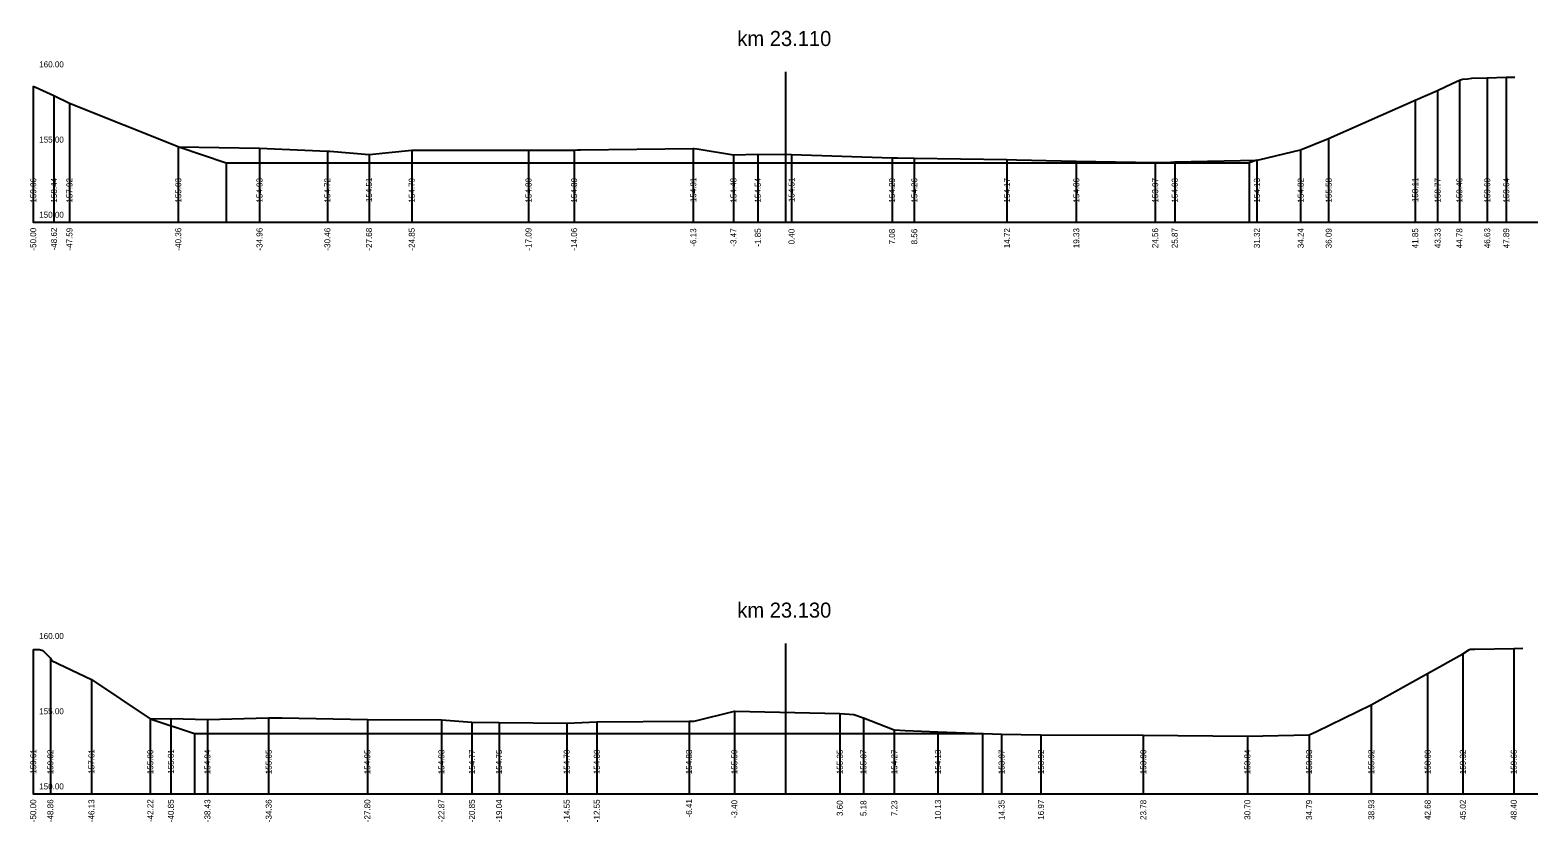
# Model space of a CAD drawing. Extents: x -582678 to -581845, y -1210354 to -1210235.
# Drawn here: x -581945.7 to -581845.4, y -1210306.7 to -1210254.1 of the extents above; entities that cross this region are included whole.
import ezdxf

# ---------------------------------------------------------------- set-up
doc = ezdxf.new("R2010")
doc.units = 0
for name, color, linetype in [('_N_osa', 7, 'Continuous'), ('_N_pomocná', 7, 'Continuous'), ('_N_tučná', 7, 'Continuous'), ('_S_popis', 7, 'Continuous'), ('_S_popis_oprav!', 7, 'Continuous'), ('_S_tenká', 7, 'Continuous'), ('_S_velmi_tenká', 7, 'Continuous')]:
    doc.layers.add(name, color=color, linetype=linetype)

msp = doc.modelspace()

# ---------------------------------------------------------------- linework, layer by layer
at = {"layer": '_N_osa'}
for p, q in [((-581895.45, -1210256.87), (-581895.45, -1210266.87)), ((-581895.45, -1210294.87), (-581895.45, -1210304.87))]:
    msp.add_line(p, q, dxfattribs=at)
at = {"layer": '_N_pomocná'}
for p, q in [((-581932.63, -1210262.91), (-581932.63, -1210266.87)), ((-581864.63, -1210262.91), (-581864.63, -1210266.87)), ((-581934.72, -1210300.85), (-581934.72, -1210304.87)), ((-581882.35, -1210300.85), (-581882.35, -1210304.87))]:
    msp.add_line(p, q, dxfattribs=at)
at = {"layer": '_N_tučná'}
for p, q in [((-581935.78, -1210261.85), (-581932.63, -1210262.91)), ((-581864.12, -1210262.74), (-581864.63, -1210262.91)), ((-581937.67, -1210299.87), (-581934.72, -1210300.85))]:
    msp.add_line(p, q, dxfattribs=at)
for points in [[(-581932.63, -1210262.91), (-581864.63, -1210262.91)], [(-581934.72, -1210300.85), (-581882.35, -1210300.85)]]:
    msp.add_lwpolyline(points, dxfattribs=at)
at = {"layer": '_S_tenká'}
for p, q in [((-581945.45, -1210266.87), (-581845.45, -1210266.87)), ((-581945.45, -1210304.87), (-581845.45, -1210304.87))]:
    msp.add_line(p, q, dxfattribs=at)
for points in [[(-581945.45, -1210257.81), (-581945.3, -1210257.88), (-581944.07, -1210258.43), (-581943.04, -1210258.95), (-581935.81, -1210261.84), (-581935.78, -1210261.85), (-581935.77, -1210261.85), (-581930.41, -1210261.94), (-581925.9, -1210262.15), (-581925.73, -1210262.14), (-581923.13, -1210262.36), (-581920.29, -1210262.08), (-581919.97, -1210262.07), (-581912.53, -1210262.07), (-581909.5, -1210262.07), (-581909.42, -1210262.07), (-581909.27, -1210262.06), (-581909.07, -1210262.06), (-581901.58, -1210261.96), (-581901.52, -1210261.96), (-581901.32, -1210261.99), (-581898.91, -1210262.39), (-581897.29, -1210262.33), (-581895.05, -1210262.36), (-581888.37, -1210262.58), (-581888.01, -1210262.59), (-581886.89, -1210262.61), (-581880.73, -1210262.7), (-581880.1, -1210262.71), (-581876.12, -1210262.81), (-581870.88, -1210262.9), (-581870.12, -1210262.89), (-581869.58, -1210262.84), (-581864.12, -1210262.74), (-581863.9, -1210262.7), (-581861.21, -1210262.05), (-581859.35, -1210261.29), (-581853.6, -1210258.76), (-581852.11, -1210258.1), (-581851.13, -1210257.64), (-581850.66, -1210257.41), (-581850.45, -1210257.35), (-581850.12, -1210257.34), (-581849.83, -1210257.29), (-581848.81, -1210257.27), (-581847.55, -1210257.23), (-581847.12, -1210257.22), (-581846.98, -1210257.22)], [(-581945.45, -1210295.26), (-581945.35, -1210295.26), (-581945.03, -1210295.27), (-581944.8, -1210295.34), (-581944.31, -1210295.85), (-581944.23, -1210296), (-581941.58, -1210297.26), (-581937.67, -1210299.87), (-581936.3, -1210299.86), (-581933.87, -1210299.93), (-581929.8, -1210299.82), (-581929.36, -1210299.82), (-581928.93, -1210299.82), (-581923.24, -1210299.92), (-581918.32, -1210299.94), (-581916.29, -1210300.1), (-581914.49, -1210300.12), (-581909.99, -1210300.17), (-581907.99, -1210300.07), (-581901.86, -1210300.04), (-581901.6, -1210300.04), (-581901.53, -1210300.03), (-581898.85, -1210299.37), (-581898.81, -1210299.37), (-581891.84, -1210299.52), (-581890.9, -1210299.58), (-581890.27, -1210299.8), (-581888.22, -1210300.6), (-581887.5, -1210300.65), (-581885.32, -1210300.74), (-581881.09, -1210300.9), (-581878.47, -1210300.95), (-581871.67, -1210300.97), (-581864.75, -1210301.03), (-581860.65, -1210300.94), (-581860.16, -1210300.71), (-581856.52, -1210298.95), (-581852.77, -1210296.87), (-581850.43, -1210295.55), (-581849.99, -1210295.27), (-581849.93, -1210295.25), (-581849.64, -1210295.24), (-581847.05, -1210295.21), (-581846.45, -1210295.18)]]:
    msp.add_lwpolyline(points, dxfattribs=at)
at = {"layer": '_S_velmi_tenká'}
for points in [[(-581850.66, -1210257.41), (-581850.66, -1210266.87), (-581850.66, -1210266.87), (-581850.66, -1210266.87)], [(-581848.81, -1210257.27), (-581848.81, -1210266.87), (-581848.81, -1210266.87), (-581848.81, -1210266.87)], [(-581847.55, -1210257.23), (-581847.55, -1210266.87), (-581847.55, -1210266.87), (-581847.55, -1210266.87)], [(-581945.45, -1210257.81), (-581945.45, -1210266.87), (-581945.45, -1210266.87), (-581945.45, -1210266.87)], [(-581944.07, -1210258.43), (-581944.07, -1210266.87), (-581944.07, -1210266.87), (-581944.07, -1210266.87)], [(-581852.11, -1210258.1), (-581852.11, -1210266.87), (-581852.11, -1210266.87), (-581852.11, -1210266.87)], [(-581943.04, -1210258.95), (-581943.04, -1210266.87), (-581943.04, -1210266.87), (-581943.04, -1210266.87)], [(-581853.6, -1210258.76), (-581853.6, -1210266.87), (-581853.6, -1210266.87), (-581853.6, -1210266.87)], [(-581859.35, -1210261.29), (-581859.35, -1210266.87), (-581859.35, -1210266.87), (-581859.35, -1210266.87)], [(-581935.81, -1210261.84), (-581935.81, -1210266.87), (-581935.81, -1210266.87), (-581935.81, -1210266.87)], [(-581930.41, -1210261.94), (-581930.41, -1210266.87), (-581930.41, -1210266.87), (-581930.41, -1210266.87)], [(-581925.9, -1210262.15), (-581925.9, -1210266.87), (-581925.9, -1210266.87), (-581925.9, -1210266.87)], [(-581923.13, -1210262.36), (-581923.13, -1210266.87), (-581923.13, -1210266.87), (-581923.13, -1210266.87)], [(-581920.29, -1210262.08), (-581920.29, -1210266.87), (-581920.29, -1210266.87), (-581920.29, -1210266.87)], [(-581912.53, -1210262.07), (-581912.53, -1210266.87), (-581912.53, -1210266.87), (-581912.53, -1210266.87)], [(-581909.5, -1210262.07), (-581909.5, -1210266.87), (-581909.5, -1210266.87), (-581909.5, -1210266.87)], [(-581901.58, -1210261.96), (-581901.58, -1210266.87), (-581901.58, -1210266.87), (-581901.58, -1210266.87)], [(-581898.91, -1210262.39), (-581898.91, -1210266.87), (-581898.91, -1210266.87), (-581898.91, -1210266.87)], [(-581897.29, -1210262.33), (-581897.29, -1210266.87), (-581897.29, -1210266.87), (-581897.29, -1210266.87)], [(-581895.05, -1210262.36), (-581895.05, -1210266.87), (-581895.05, -1210266.87), (-581895.05, -1210266.87)], [(-581861.21, -1210262.05), (-581861.21, -1210266.87), (-581861.21, -1210266.87), (-581861.21, -1210266.87)], [(-581888.37, -1210262.58), (-581888.37, -1210266.87), (-581888.37, -1210266.87), (-581888.37, -1210266.87)], [(-581886.89, -1210262.61), (-581886.89, -1210266.87), (-581886.89, -1210266.87), (-581886.89, -1210266.87)], [(-581880.73, -1210262.7), (-581880.73, -1210266.87), (-581880.73, -1210266.87), (-581880.73, -1210266.87)], [(-581876.12, -1210262.81), (-581876.12, -1210266.87), (-581876.12, -1210266.87), (-581876.12, -1210266.87)], [(-581870.88, -1210262.9), (-581870.88, -1210266.87), (-581870.88, -1210266.87), (-581870.88, -1210266.87)], [(-581869.58, -1210262.84), (-581869.58, -1210266.87), (-581869.58, -1210266.87), (-581869.58, -1210266.87)], [(-581864.12, -1210262.74), (-581864.12, -1210266.87), (-581864.12, -1210266.87), (-581864.12, -1210266.87)], [(-581945.45, -1210295.26), (-581945.45, -1210304.87), (-581945.45, -1210304.87), (-581945.45, -1210304.87)], [(-581850.43, -1210295.55), (-581850.43, -1210304.87), (-581850.43, -1210304.87), (-581850.43, -1210304.87)], [(-581847.05, -1210295.21), (-581847.05, -1210304.87), (-581847.05, -1210304.87), (-581847.05, -1210304.87)], [(-581944.31, -1210295.85), (-581944.31, -1210304.87), (-581944.31, -1210304.87), (-581944.31, -1210304.87)], [(-581941.58, -1210297.26), (-581941.58, -1210304.87), (-581941.58, -1210304.87), (-581941.58, -1210304.87)], [(-581852.77, -1210296.87), (-581852.77, -1210304.87), (-581852.77, -1210304.87), (-581852.77, -1210304.87)], [(-581898.85, -1210299.37), (-581898.85, -1210304.87), (-581898.85, -1210304.87), (-581898.85, -1210304.87)], [(-581891.84, -1210299.52), (-581891.84, -1210304.87), (-581891.84, -1210304.87), (-581891.84, -1210304.87)], [(-581856.52, -1210298.95), (-581856.52, -1210304.87), (-581856.52, -1210304.87), (-581856.52, -1210304.87)], [(-581937.67, -1210299.87), (-581937.67, -1210304.87), (-581937.67, -1210304.87), (-581937.67, -1210304.87)], [(-581936.3, -1210299.86), (-581936.3, -1210304.87), (-581936.3, -1210304.87), (-581936.3, -1210304.87)], [(-581933.87, -1210299.93), (-581933.87, -1210304.87), (-581933.87, -1210304.87), (-581933.87, -1210304.87)], [(-581929.8, -1210299.82), (-581929.8, -1210304.87), (-581929.8, -1210304.87), (-581929.8, -1210304.87)], [(-581923.24, -1210299.92), (-581923.24, -1210304.87), (-581923.24, -1210304.87), (-581923.24, -1210304.87)], [(-581918.32, -1210299.94), (-581918.32, -1210304.87), (-581918.32, -1210304.87), (-581918.32, -1210304.87)], [(-581916.29, -1210300.1), (-581916.29, -1210304.87), (-581916.29, -1210304.87), (-581916.29, -1210304.87)], [(-581914.49, -1210300.12), (-581914.49, -1210304.87), (-581914.49, -1210304.87), (-581914.49, -1210304.87)], [(-581909.99, -1210300.17), (-581909.99, -1210304.87), (-581909.99, -1210304.87), (-581909.99, -1210304.87)], [(-581907.99, -1210300.07), (-581907.99, -1210304.87), (-581907.99, -1210304.87), (-581907.99, -1210304.87)], [(-581901.86, -1210300.04), (-581901.86, -1210304.87), (-581901.86, -1210304.87), (-581901.86, -1210304.87)], [(-581890.27, -1210299.8), (-581890.27, -1210304.87), (-581890.27, -1210304.87), (-581890.27, -1210304.87)], [(-581888.22, -1210300.6), (-581888.22, -1210304.87), (-581888.22, -1210304.87), (-581888.22, -1210304.87)], [(-581885.32, -1210300.74), (-581885.32, -1210304.87), (-581885.32, -1210304.87), (-581885.32, -1210304.87)], [(-581881.09, -1210300.9), (-581881.09, -1210304.87), (-581881.09, -1210304.87), (-581881.09, -1210304.87)], [(-581878.47, -1210300.95), (-581878.47, -1210304.87), (-581878.47, -1210304.87), (-581878.47, -1210304.87)], [(-581871.67, -1210300.97), (-581871.67, -1210304.87), (-581871.67, -1210304.87), (-581871.67, -1210304.87)], [(-581864.75, -1210301.03), (-581864.75, -1210304.87), (-581864.75, -1210304.87), (-581864.75, -1210304.87)], [(-581860.65, -1210300.94), (-581860.65, -1210304.87), (-581860.65, -1210304.87), (-581860.65, -1210304.87)]]:
    msp.add_lwpolyline(points, dxfattribs=at)

# ---------------------------------------------------------------- texts
at = {"layer": '_S_popis'}
for s, p in [('160.00', (-581945.05, -1210256.57)), ('155.00', (-581945.05, -1210261.57)), ('150.00', (-581945.05, -1210266.57)), ('160.00', (-581945.05, -1210294.57)), ('155.00', (-581945.05, -1210299.57)), ('150.00', (-581945.05, -1210304.57))]:
    msp.add_text(s, height=0.4, dxfattribs=at).set_placement(p)
for s, p in [('159.06', (-581945.25, -1210265.56)), ('158.44', (-581943.87, -1210265.56)), ('157.92', (-581942.84, -1210265.56)), ('155.03', (-581935.61, -1210265.56)), ('154.93', (-581930.21, -1210265.56)), ('154.72', (-581925.7, -1210265.56)), ('154.51', (-581922.93, -1210265.53)), ('154.79', (-581920.09, -1210265.56)), ('154.80', (-581912.33, -1210265.56)), ('154.80', (-581909.3, -1210265.56)), ('154.91', (-581901.38, -1210265.53)), ('154.48', (-581898.71, -1210265.56)), ('154.54', (-581897.09, -1210265.56)), ('154.51', (-581894.85, -1210265.53)), ('154.29', (-581888.17, -1210265.56)), ('154.26', (-581886.69, -1210265.56)), ('154.17', (-581880.53, -1210265.56)), ('154.06', (-581875.92, -1210265.56)), ('153.97', (-581870.68, -1210265.56)), ('154.03', (-581869.38, -1210265.56)), ('154.13', (-581863.92, -1210265.56)), ('154.82', (-581861.01, -1210265.56)), ('155.58', (-581859.15, -1210265.56)), ('158.11', (-581853.4, -1210265.53)), ('158.77', (-581851.91, -1210265.56)), ('159.46', (-581850.46, -1210265.56)), ('159.60', (-581848.61, -1210265.56)), ('159.64', (-581847.35, -1210265.56)), ('-50.00', (-581945.25, -1210268.75)), ('-48.62', (-581943.87, -1210268.74)), ('-47.59', (-581942.84, -1210268.75)), ('-40.36', (-581935.61, -1210268.75)), ('-34.96', (-581930.21, -1210268.75)), ('-30.46', (-581925.7, -1210268.75)), ('-27.68', (-581922.93, -1210268.75)), ('-24.85', (-581920.09, -1210268.75)), ('-17.09', (-581912.33, -1210268.75)), ('-14.06', (-581909.3, -1210268.75)), ('-6.13', (-581901.38, -1210268.49)), ('-3.47', (-581898.71, -1210268.49)), ('-1.85', (-581897.09, -1210268.49)), ('0.40', (-581894.85, -1210268.34)), ('7.08', (-581888.17, -1210268.34)), ('8.56', (-581886.69, -1210268.34)), ('14.72', (-581880.53, -1210268.59)), ('19.33', (-581875.92, -1210268.59)), ('24.56', (-581870.68, -1210268.59)), ('25.87', (-581869.38, -1210268.59)), ('31.32', (-581863.92, -1210268.59)), ('34.24', (-581861.01, -1210268.59)), ('36.09', (-581859.15, -1210268.6)), ('41.85', (-581853.4, -1210268.6)), ('43.33', (-581851.91, -1210268.59)), ('44.78', (-581850.46, -1210268.6)), ('46.63', (-581848.61, -1210268.59)), ('47.89', (-581847.35, -1210268.6)), ('159.61', (-581945.25, -1210303.53)), ('159.02', (-581944.11, -1210303.56)), ('157.61', (-581941.38, -1210303.53)), ('155.00', (-581937.47, -1210303.56)), ('155.01', (-581936.1, -1210303.53)), ('154.94', (-581933.67, -1210303.56)), ('155.05', (-581929.6, -1210303.56)), ('154.95', (-581923.04, -1210303.56)), ('154.93', (-581918.12, -1210303.56)), ('154.77', (-581916.09, -1210303.56)), ('154.75', (-581914.29, -1210303.56)), ('154.70', (-581909.79, -1210303.56)), ('154.80', (-581907.79, -1210303.56)), ('154.83', (-581901.66, -1210303.56)), ('155.50', (-581898.65, -1210303.56)), ('155.35', (-581891.64, -1210303.56)), ('155.07', (-581890.07, -1210303.56)), ('154.27', (-581888.02, -1210303.56)), ('154.13', (-581885.12, -1210303.56)), ('153.97', (-581880.89, -1210303.56)), ('153.92', (-581878.27, -1210303.56)), ('153.90', (-581871.47, -1210303.56)), ('153.84', (-581864.55, -1210303.56)), ('153.93', (-581860.45, -1210303.56)), ('155.92', (-581856.32, -1210303.56)), ('158.00', (-581852.57, -1210303.56)), ('159.32', (-581850.23, -1210303.56)), ('159.66', (-581846.85, -1210303.56)), ('-50.00', (-581945.25, -1210306.75)), ('-48.86', (-581944.11, -1210306.75)), ('-46.13', (-581941.38, -1210306.75)), ('-42.22', (-581937.47, -1210306.74)), ('-40.85', (-581936.1, -1210306.75)), ('-38.43', (-581933.67, -1210306.75)), ('-34.36', (-581929.6, -1210306.75)), ('-27.80', (-581923.04, -1210306.75)), ('-22.87', (-581918.12, -1210306.75)), ('-20.85', (-581916.09, -1210306.75)), ('-19.04', (-581914.29, -1210306.75)), ('-14.55', (-581909.79, -1210306.75)), ('-12.55', (-581907.79, -1210306.75)), ('-6.41', (-581901.66, -1210306.43)), ('-3.40', (-581898.65, -1210306.49)), ('3.60', (-581891.64, -1210306.34)), ('5.18', (-581890.07, -1210306.34)), ('7.23', (-581888.02, -1210306.34)), ('10.13', (-581885.12, -1210306.59)), ('14.35', (-581880.89, -1210306.6)), ('16.97', (-581878.27, -1210306.59)), ('23.78', (-581871.47, -1210306.6)), ('30.70', (-581864.55, -1210306.59)), ('34.79', (-581860.45, -1210306.6)), ('38.93', (-581856.32, -1210306.59)), ('42.68', (-581852.57, -1210306.6)), ('45.02', (-581850.23, -1210306.59)), ('48.40', (-581846.85, -1210306.59))]:
    msp.add_text(s, height=0.4, rotation=90, dxfattribs=at).set_placement(p)
at = {"layer": '_S_popis_oprav!'}
for s, p in [('km 23.110', (-581898.65, -1210255.15)), ('km 23.130', (-581898.65, -1210293.15))]:
    msp.add_text(s, height=1, dxfattribs=at).set_placement(p)

doc.saveas('drawing.dxf')
